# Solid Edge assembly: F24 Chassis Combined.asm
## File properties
Title: F24 CHASSIS
Subject: MAIN CHASSIS
Author: chasteen
Template: Ansi Inch Assembly.asm
Last saved by: z0cbxm
Revision: 135
Application: Solid Edge
Document Number: F24 - DWG#16
Revision: A
Weld Bead Density: 0.000 lbm/in^3
property 32: steel
property 3: Low Carbon Steel
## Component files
F24 Main Chassis Bottom -Complete.asm
F24 Main Chassis Top.asm
F24 Chassis Weldment.asm
SquareTubing 1.25x1.25x.06.par
Front Plate.psm
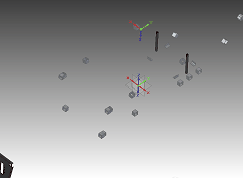
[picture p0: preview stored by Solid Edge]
